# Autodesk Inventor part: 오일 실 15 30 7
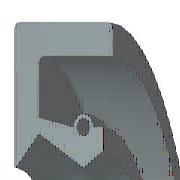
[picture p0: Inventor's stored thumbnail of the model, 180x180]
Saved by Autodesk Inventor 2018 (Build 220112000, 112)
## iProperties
IsCustomPart: 1
Created: 2012-02
Part Number: 오일 실 15 30 7
Material: 고무
Description: 오일-실
Document SubType Name: Modeling
Standard: KS B 2804
Designer: mduedu
Standards Organization: KS
Language: ko-KR
Size Designation: D - 15 30 7
Categories: <MemberInstance><Categories><Category DisplayName="샤프트 부품" InternalName="7f7aeb1f-a693-4053-b835-cee3144e0d98" Mnemonic="SHFT"><Category DisplayName="실링" Intern
Density: 0.93 g/cm^3
Appearance: 고무 - 검은색 - 버전 1.1
Author: mduedu
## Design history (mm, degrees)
revolve "본체" stored, may be unused: angle "d17" = 90 deg
revolve "스프링1" stored, may be unused: angle "d18" = 90 deg
body "Solid1"
sketch "스케치1"
  geometry: L1 (0, 15)-(7, 15); L2 (7, 13.25)-(1.75, 13.25); L3 (1.75, 9.25)-(4.9, 7.5); L4 (4.9, 7.5)-(0, 7.5); L5 (0, 0)-(9.586, 0) reference; L6 (4.9, 7.5)-(6.3, 8.375); L7 (0, 18)-(0, -3) reference; L8 (-1.941, 0)-(11.507, 0) reference; L9 (4.2, 9.6)-(1.75, 10.09); L10 (1.75, 10.09)-(1.75, 13.25); L11 (0, 15)-(0, 7.588); L12 (4.9, 7.5)-(0, 7.5); L13 (1.75, 9.25)-(0.152, 7.528); L14 (7, 15)-(7, 13.25); L15 (5.6, 9.6)-(6.3, 9.6); L16 (6.3, 9.6)-(6.3, 8.375); C1 r 0.455 at (4.9, 9.6); A1 r 0.7 centre (4.9, 9.6) between (5.6, 9.6) and (4.2, 9.6); A2 r 0.088 centre (0.088, 7.588) between (0, 7.588) and (0.152, 7.528); 1 further point
  constraints: 28 end point, 5 horizontal alignment, 5 point on line, 4 point on circle, 4 vertical alignment, 3 centre point, 3 tangent, 2 collinear, 2 horizontal, 2 perpendicular, 1 coincident, 1 parallel
  dimensions: "d0" = 30 diameter of L1 L5 (= SD2); "d1" = 1.75 distance of L1.end L2.start (= SD); "d2" = 0.91 diameter of C1 (= SPDI); "d3" = 1.4 diameter of A1 (= SPDA); "d4" = 15 diameter of L3.end L5 (= NND); "d5" = 18.5 diameter of L3.start L5 (= TKDM); "d7" = 20.18 diameter of L9.end L5 (= TKDM + 0.24 x SWDT); "d8" = 1.75 distance between parallel lines of L11 L10 (= SD); "d9" = 4.9 distance from line of L11 C1.centre (= SPDST); "d10" = 19.2 diameter of C1.centre L5 (= HLDM); "d11" = 0.0875 radius of A2 (= 0.25 x LAB); "d12" = 6.3 distance between parallel lines of L11 L16 (= SDI); "d13" = 16.75 diameter of L6.end L5 (= ABDM); "d14" = 7 distance from line of L11 L1.end (= SWDT)
fillet "모깎기1" dims "d6" = 0.3 (= RR)
other parameters: "SD2" = 30 [user parameter; used in 1 equation term], "SWDT" = 7 [user parameter; used in 2 equation terms], "RR" = 0.3 [user parameter; used in 1 equation term], "SD" = 1.75 [user parameter; used in 2 equation terms], "NND" = 15 [user parameter; used in 1 equation term], "SPDA" = 1.4 [user parameter; used in 1 equation term], "SPDI" = 0.91 [user parameter; used in 1 equation term], "TKDM" = 18.5 [user parameter; used in 2 equation terms], "HLDM" = 19.2 [user parameter; used in 1 equation term], "ABDM" = 16.75 [user parameter; used in 1 equation term], "SDI" = 6.3 [user parameter; used in 1 equation term], "SPDST" = 4.9 [user parameter; used in 1 equation term], "LAB" = 0.35 [user parameter; used in 1 equation term], "d15" = 0, "d16" = 0, "d19" = 0
